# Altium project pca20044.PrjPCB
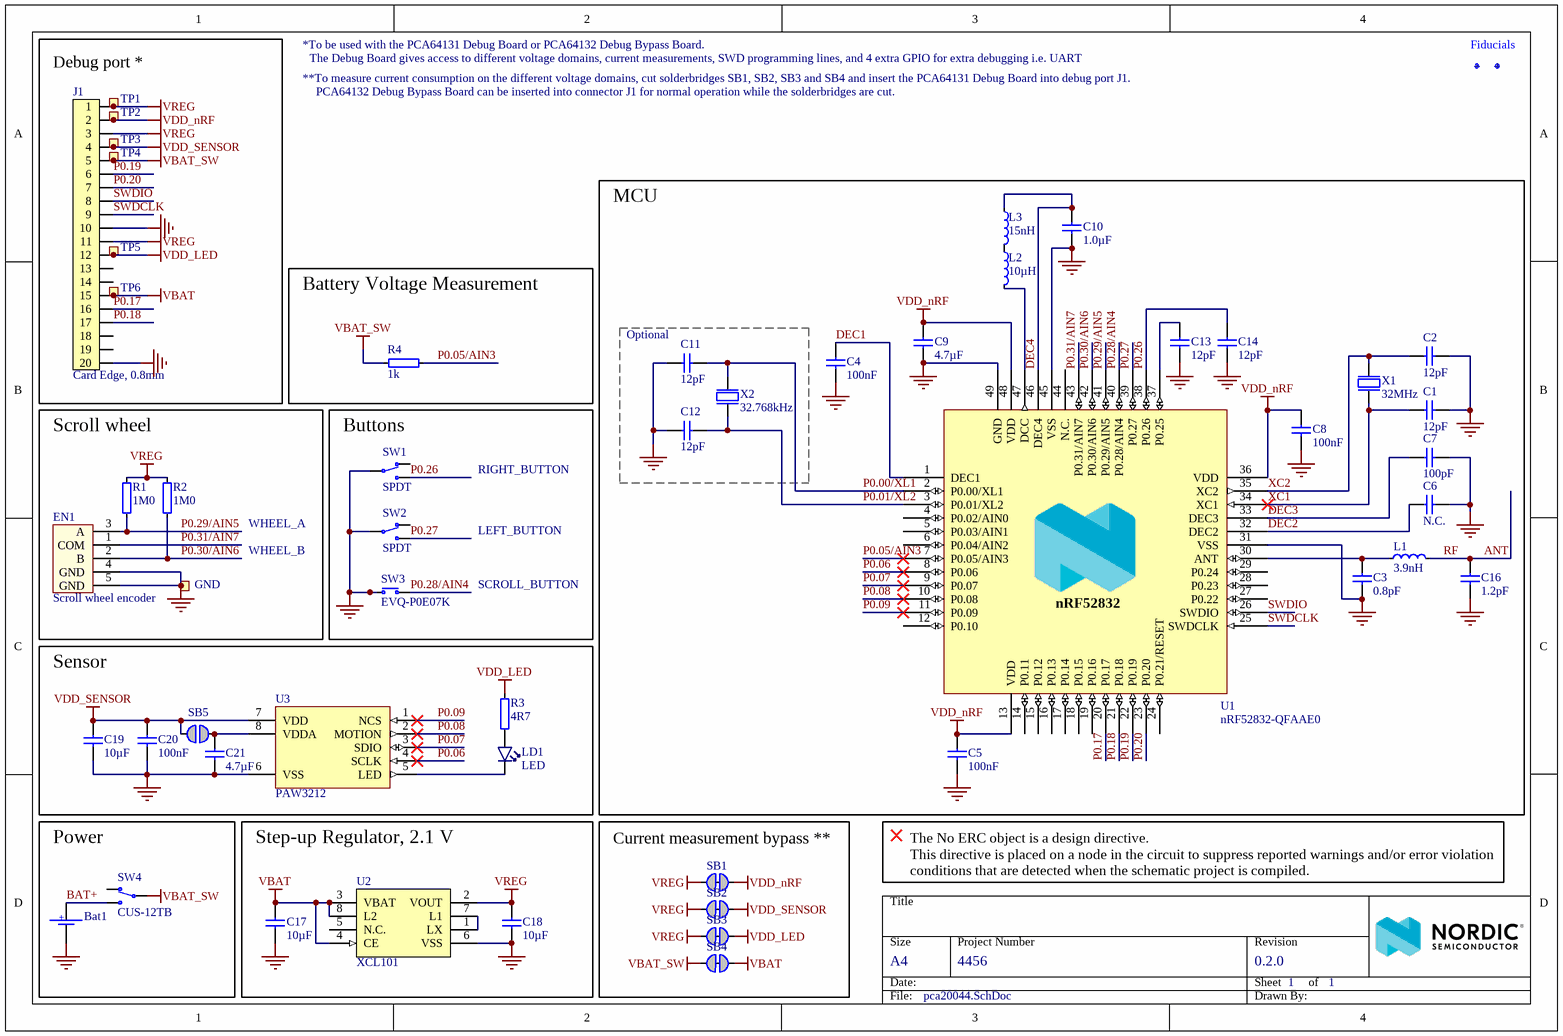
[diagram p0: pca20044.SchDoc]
SurfaceFinish: ENIG Gold; SoldermaskColor: Blue; SilkscreenColor: White; Revision: 0.2.0; ProjectNumber: 4456; ProjectName: nRF52 Desktop; PCBStackup: 2001; PCBRevision: 0013MASI; PCBNumber: 400440; PCAName: PCA20044; Organization: Nordic Semiconductor; NrOfLayers: 2; BoardTitle: nRF52832/nRF52810 Desktop Mouse; BoardThickness: 1.2mm; Author: MASI
1 sheet, 54 parts. Net scope: global (net labels, ports and power ports of the same name join across sheets).
Board file: 400440.PcbDoc

## Sheet pca20044.SchDoc: =BoardTitle
size A4; Organization: Nordic Semiconductor; Revision: 0.2.0; SheetNumber: 1; SheetTotal: 1; Author: MASI; CompanyName: Nordic Semiconductor; DrawnBy: MASI

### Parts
Bat1  (no value)  [MORFFLUOA_Battery_Spring]
C1  12pF  [CAPC1005X04L]
C2  12pF  [CAPC1005X04L]
C3  0.8pF  [CAPC1005X04L]
C4  100nF  [CAPC1005X04L]
C5  100nF  [CAPC1005X04L]
C6  N.C.  [CAPC1005X04L]
C7  100pF  [CAPC1005X04L]
C8  100nF  [CAPC1005X04L]
C9  4.7µF  [CAPC1608X06L]
C10  1.0µF  [CAPC1608X06L]
C11  12pF  [CAPC1005X04L]
C12  12pF  [CAPC1005X04L]
C13  12pF  [CAPC1005X04L]
C14  12pF  [CAPC1005X04L]
C16  1.2pF  [CAPC1005X04L]
C17  10µF  [CAPC1608X06L]
C18  10µF  [CAPC1608X06L]
C19  10µF  [CAPC1608X06L]
C20  100nF  [CAPC1608X06L]
C21  4.7µF  [CAPC1608X06L]
EN1  Scroll wheel encoder  [M01_Scroll_Wheel_Encoder]
Fid1  Fiducial mark  [Fiducial]  (value not drawn)
Fid2  Fiducial mark  [Fiducial]  (value not drawn)
GND  TP  [TESTPAD-TH]  (value not drawn)  (no BOM)
J1  Card Edge, 0.8mm  [10056847-101LF]
L1  3.9nH  [INDC1005X04L]
L2  10µH  [INDC1608X06L]
L3  15nH  [INDC1005X04L]
LD1  LED  [LED_5MM_RA]
R1  1M0  [RESC1005X04L]
R2  1M0  [RESC1005X04L]
R3  4R7  [RESC1005X04L]
R4  1k  [RESC1005X04L]
SB1  Solderbridge  [Solderbridge_Shorted_Power]  (value not drawn)  (net tie, no BOM)
SB2  Solderbridge  [Solderbridge_Shorted_Power]  (value not drawn)  (net tie, no BOM)
SB3  Solderbridge  [Solderbridge_Shorted_Power]  (value not drawn)  (net tie, no BOM)
SB4  Solderbridge  [Solderbridge_Shorted_Power]  (value not drawn)  (net tie, no BOM)
SB5  Solderbridge  [Solderbridge]  (value not drawn)  (no BOM)
SW1  SPDT  [D2F-F]
SW2  SPDT  [D2F-F]
SW3  EVQ-P0E07K  [EVQP0E07K]
SW4  CUS-12TB  [CUS-12B]
TP1  Ø1.5mm,SMD  [TP_SMD_Ø1.5mm]  (value not drawn)  (no BOM)
TP2  Ø1.5mm,SMD  [TP_SMD_Ø1.5mm]  (value not drawn)  (no BOM)
TP3  Ø1.5mm,SMD  [TP_SMD_Ø1.5mm]  (value not drawn)  (no BOM)
TP4  Ø1.5mm,SMD  [TP_SMD_Ø1.5mm]  (value not drawn)  (no BOM)
TP5  Ø1.5mm,SMD  [TP_SMD_Ø1.5mm]  (value not drawn)  (no BOM)
TP6  Ø1.5mm,SMD  [TP_SMD_Ø1.5mm]  (value not drawn)  (no BOM)
U1  nRF52832-QFAAE0  [QFN40P600X600X90-48N]
U2  XCL101  [CL-2025]
U3  PAW3212  [PAW3212DB-TJDT]
X1  32MHz  [BT-XTAL_2016]
X2  32.768kHz  [XTAL_3215]

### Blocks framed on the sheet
Debug port *: J1 TP1-TP6
MCU: C1-C10 C13 C14 C16 L1-L3 U1 X1
Battery Voltage Measurement: R4
Optional: C11 C12 X2
Scroll wheel: EN1 GND R1 R2
Buttons: SW1-SW3
Sensor: C19-C21 LD1 R3 SB5 U3
Power: Bat1 SW4
Step-up Regulator, 2.1 V: C17 C18 U2
Current measurement bypass **: SB1-SB4

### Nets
GND: Bat1.2 C1.2 C2.2 C3.1 C4.2 C5.2 C6.1 C7.2 C8.2 C9.2 C10.1 C11.2 C12.2 C13.2 C14.2 C16.2 C17.1 C18.1 C19.1 C20.1 C21.1 EN1.4(GND) EN1.5(GND) GND.1 J1.10 J1.20 SW1.2(COM) SW2.2(COM) SW3.2(COM) U1.31(VSS) U1.45(VSS) U1.49(GND) U2.6(VSS) U2.9(VSS) U3.6(VSS) X1.2(GND) X1.4(GND)
VBAT: C17.2 J1.15 SB4.2 TP6.1 U2.3(VBAT) U2.4(CE) U2.8(L2)
VBAT_SW: J1.5 R4.1 SB4.1 SW4.2(COM) TP4.1
VDD_LED: J1.12 R3.2 SB3.2 TP5.1
VDD_nRF: C5.1 C8.1 C9.1 J1.2 SB1.2 TP2.1 U1.13(VDD) U1.36(VDD) U1.48(VDD)
VDD_SENSOR: C19.2 C20.2 J1.4 SB2.2 SB5.1 TP3.1 U3.7(VDD)
VREG: C18.2 J1.1 J1.3 J1.11 R1.2 R2.2 SB1.1 SB2.1 SB3.1 TP1.1 U2.2(VOUT)
ANT: C16.1 L1.2  [also labelled RF]
BAT+: Bat1.1 SW4.3(N.O)
DEC1: C4.1 U1.1(DEC1)
DEC2: C6.2 U1.32(DEC2)
DEC3: C7.1 U1.33(DEC3)
DEC4: C10.2 L3.1 U1.46(DEC4)
P0.00/XL1: C11.1 U1.2(P0.00/XL1) X2.1(inp)
P0.01/XL2: C12.1 U1.3(P0.01/XL2) X2.2(out)
P0.05/AIN3: R4.2 U1.7(P0.05/AIN3)
P0.06: U1.8(P0.06) U3.4(SCLK)
P0.07: U1.9(P0.07) U3.3(SDIO)
P0.08: U1.10(P0.08) U3.2(MOTION)
P0.09: U1.11(P0.09) U3.1(NCS)
P0.17: J1.16 U1.20(P0.17)
P0.18: J1.17 U1.21(P0.18)
P0.19: J1.6 U1.22(P0.19)
P0.20: J1.7 U1.23(P0.20)
P0.26: C14.1 SW1.3(N.O) U1.38(P0.26)
P0.27: SW2.3(N.O) U1.39(P0.27)
P0.28/AIN4: SW3.1(N.O) U1.40(P0.28/AIN4)
P0.29/AIN5: EN1.3(A) R1.1 U1.41(P0.29/AIN5)
P0.30/AIN6: EN1.2(B) R2.1 U1.42(P0.30/AIN6)
P0.31/AIN7: EN1.1(COM) U1.43(P0.31/AIN7)
SWDCLK: J1.9 U1.25(SWDCLK)
SWDIO: J1.8 U1.26(SWDIO)
XC1: C1.1 U1.34(XC1) X1.1(inp)
XC2: C2.1 U1.35(XC2) X1.3(out)
NetC3_2: C3.2 L1.1 U1.30(ANT)
NetC13_1: C13.1 U1.37(P0.25)
NetC21_2: C21.2 SB5.2 U3.8(VDDA)
NetL2_1: L2.1 L3.2
NetL2_2: L2.2 U1.47(DCC)
NetLD1_1: LD1.1(C) U3.5(LED)
NetLD1_2: LD1.2(A) R3.1
NetU2_1: U2.1(LX) U2.7(L1)

Not connected (* = marked no-connect by the designer): J1 13 14 18 19; SW1 1(N.C); SW2 1(N.C); SW4 1(N.C); U1 4(P0.02/AIN0) 5(P0.03/AIN1) 6(P0.04/AIN2) 12(P0.10) 14(P0.11) 15(P0.12) 16(P0.13) 17(P0.14) 18(P0.15) 19(P0.16) 24(P0.21/RESET) 27(P0.22) 28(P0.23) 29(P0.24) 44(N.C.); U2 5(N.C.)

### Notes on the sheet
- **To measure current consumption on the different voltage domains, cut solderbridges SB1, SB2, SB3 and SB4 and insert the PCA64131 Debug Board into debug port J1.
- *To be used with the PCA64131 Debug Board or PCA64132 Debug Bypass Board.
- The Debug Board gives access to different voltage domains, current measurements, SWD programming lines, and 4 extra GPIO for extra debugging i.e. UART
- PCA64132 Debug Bypass Board can be inserted into connector J1 for normal operation while the solderbridges are cut.
- Fiducials
- RIGHT_BUTTON
- WHEEL_A
- WHEEL_B
- LEFT_BUTTON
- SCROLL_BUTTON
- The No ERC object is a design directive.
  This directive is placed on a node in the circuit to suppress reported warnings and/or error violation conditions that are detected when the schematic project is compiled.

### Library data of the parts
Bat1 = MORFFLOUA Battery Spring: Battery Spring, 1xAA; Artikkelnr Noca: N.A.
C1 C2 C11-C14 = C0402-12p: Capacitor, NP0, ±2%; Note: 50V; Artikkelnr Noca: 20029159; Artikkelnr Simpro: N.A.
C3 = C0402-0.8p: Capacitor, NP0, ±5%; Note: 50V; Artikkelnr Noca: 20029147; Artikkelnr Simpro: N.A.
C4 C5 C8 = C0402-100n: Capacitor, X7R, ±10%; Note: 16V; Artikkelnr Noca: 20039200; Artikkelnr Simpro: N.A.
C6 = C0402-N.C.: Not mounted; Note: Chip Cap; Artikkelnr Noca: N.A.
C7 = C0402-100p: Capacitor, NP0, ±5%; Note: 50V; Artikkelnr Noca: 20029135; Artikkelnr Simpro: N.A.
C9 = C0603-4µ7: Capacitor, X5R, ±10%; Note: 6.3V; Artikkelnr Noca: 20069060; Artikkelnr Simpro: N.A.
C10 = C0603-1µ0: Capacitor, X7R, ±10%; Note: 16V; Artikkelnr Noca: 20039335; Artikkelnr Simpro: N.A.
C16 = C0402-1.2p: Capacitor, NP0, ±0.1pF; Manufacturer: N.A.; Part number IPS: 00000005410; Note: 50V; Artikkelnr Noca: 20029157; Pad Count: 2
C17-C19 = C0603-10µ: Capacitor, X5R, ±20%; Part number IPS: 00000007785; Note: 6.3V; Artikkelnr Noca: 20039234
C20 = C0603-100n: Chip Cap 0603; Note: Chip Cap 1%; Artikkelnr Noca: N.A.
C21 = C0603-4µ7: Capacitor, X5R, ±10%; Part number IPS: 00000007783; Note: 6.3V; Artikkelnr Noca: 20069060
EN1 = M01_Scroll_wheel_encoder, 9mm: Scroll wheel encoder, 9mm; Artikkelnr Noca: N.A.
Fid1 Fid2 = Fid-Mark: Artikkelnr Noca: N.A.
GND = Testpoint TH: Testpoint, through hole; Artikkelnr Noca: N.A.
J1 = 10056847-101LF: 0.8mm pitch, dual edge, right angle, SMD, card edge connector; Manufacturer: FCI; Artikkelnr Noca: N.A.
L1 = L0402-3n9: High frequency chip inductor ±5%; Manufacturer: Murata; Manufacturer Part Number: LQP15MN3N9B02D; Artikkelnr Noca: 33029151; Artikkelnr Simpro: N.A.
L2 = L0603-10µ: Chip inductor, IDC,min = 50 mA, ±20%; Manufacturer: Taiyo Yuden; Manufacturer Part Number: LBMF1608T100K; 2nd source part number: 178-6105; Note: LBMF1608T100K 10µH 80mA 0603; Artikkelnr Noca: 33029314; Artikkelnr Simpro: N.A.
L3 = L0402-15n: High frequency chip inductor ±10%; Manufacturer: Taiyo Yuden; Manufacturer Part Number: HK100515NJ-T; 2nd source part number: 658-1328; Artikkelnr Noca: 33029323; Artikkelnr Simpro: N.A.
LD1 = 7383M-RNW3-APSB: LED, Red, 5mm, Vf=2.0; Manufacturer: Everlight; Artikkelnr Noca: N.A.
R1 R2 = R0402-1M0: Resistor, ±1%, 0.063W; Part number IPS: 00000006807; Note: Chip Res 1%; Artikkelnr Noca: 27049145
R3 = R0402-4R7: Resistor, ±1%, 0.063W; Part number IPS: N.A.; Note: Chip Res 1%; Artikkelnr Noca: 27049017
R4 = R0402-1k0: Resistor, ±1%, 0.063W; Part number IPS: 00000002218; Note: Chip Res 1%; Artikkelnr Noca: 27049073
SB1-SB4 = Solderbridge Shorted Power: Shorted Solderbridge Power; Artikkelnr Noca: N.A.
SB5 = Solderbridge: Artikkelnr Noca: N.A.
SW1 SW2 = D2F-F: SWITCH SNAP ACTION SPDT 1A 125V; Manufacturer: Omron; Artikkelnr Noca: N.A.
SW3 = EVQ-P0E07K: Switch tactile, SPST-NO, 0.05A, 30V; Manufacturer: Panasonic - ECG; Part number IPS: N.A.; Artikkelnr Noca: 51019119
SW4 = CUS-12TB: Low-profile slide switch, SPDT, ON-ON; Manufacturer: Copal Electronics Inc; Part number IPS: N.A.; Artikkelnr Noca: 50019081
TP1-TP6 = TP_SMD_Ø1.5MM: 1.0mm circular SMD testpad; Manufacturer: Nordic Semiconductor; Artikkelnr Noca: N.A.
U1 = nRF52832-QFAAE0: Multi-protocol Bluetooth Low Energy, ANT and 2.4GHz proprietary system-on-chip; Manufacturer: Nordic Semiconductor; Artikkelnr Noca: N.A.
U2 = XCL101A211ER-G: Inductor Built-in Step-up “micro DC/DC” Converter, VOUT=2.1V, 100mA; Manufacturer: Torex Semiconductor; Artikkelnr Noca: N.A.
U3 = PAW3212DB-TJDT: Ultra Low Power Wireless Mouse Sensor; Manufacturer: Pixart Imaging inc; Artikkelnr Noca: N.A.
X1 = XTAL_SMD2016_32MHz_8pF_General: XTAL SMD 2016, 32MHz, Cl=8pF, Total Tol: ±40ppm; Note: XTAL SMD 32.000MHz; Artikkelnr Noca: N.A.
X2 = XTAL_SMD3215_32.768kHz_9pF_General: XTAL SMD 3215, 32.768kHz, Cl=9pF, Total Tol: ±50ppm; Note: XTAL SMD 32.768kHz; Artikkelnr Noca: N.A.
